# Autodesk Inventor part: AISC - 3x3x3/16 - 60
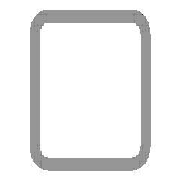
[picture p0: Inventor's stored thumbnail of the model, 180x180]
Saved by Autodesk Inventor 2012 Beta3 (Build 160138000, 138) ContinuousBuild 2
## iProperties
IsCustomPart: 1
Created: 2011-01
Part Number: AISC - 3x3x3/16 - 60
Material: Steel, Mild
Description: Tube
Document SubType Name: Modeling
Standard: ANSI
Designer: Beta-8540w
Standards Organization: ANSI
Language: en-US
Size Designation: 3x3x3/16
Categories: <MemberInstance><Categories><Category DisplayName="Structural Shapes" InternalName="089c4875-fa83-4c05-b084-43b9cc11f5ed" Mnemonic="GRDR"><CategoryParameter Dis
Stock Number: 3x3x3/16
Density: 7.86 g/cm^3
G_L: 60.000 in
G_W: 3.000 in
G_H: 3.000 in
_CCFamilyMember: 9
_CCFamilyDisplayName: ANSI AISC (Square) - Tube
_FrameMemberDoc: Frame Member File
_Version: 15.0.0
_GetPNFromCC: 1
Author: Beta-8540w
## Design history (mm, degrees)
node "Start plane"
node "End plane"
sketch "Sketch"
  geometry: L1 (-38.1, -28.575)-(-38.1, 28.575); L2 (-28.575, 38.1)-(28.575, 38.1); L3 (38.1, 28.575)-(38.1, -28.575); L4 (28.575, -38.1)-(-28.575, -38.1); L5 (-28.575, 33.337)-(28.575, 33.338); L6 (33.338, 28.575)-(33.338, -28.575); L7 (28.575, -33.337)-(-28.575, -33.338); L8 (-33.338, -28.575)-(-33.338, 28.575); L9 (0, 56.102)-(0, -56.102) reference; L10 (-56.102, 0)-(56.102, 0) reference; A1 r 9.525 centre (-28.575, -28.575) between (-38.1, -28.575) and (-28.575, -38.1); A2 r 9.525 centre (-28.575, 28.575) between (-28.575, 38.1) and (-38.1, 28.575); A3 r 9.525 centre (28.575, 28.575) between (38.1, 28.575) and (28.575, 38.1); A4 r 9.525 centre (28.575, -28.575) between (28.575, -38.1) and (38.1, -28.575); A5 r 4.763 centre (-28.575, 28.575) between (-28.575, 33.337) and (-33.338, 28.575); A6 r 4.763 centre (28.575, 28.575) between (33.338, 28.575) and (28.575, 33.338); A7 r 4.763 centre (28.575, -28.575) between (28.575, -33.337) and (33.338, -28.575); A8 r 4.763 centre (-28.575, -28.575) between (-33.338, -28.575) and (-28.575, -33.338)
  constraints: 16 end point, 16 point on circle, 8 centre point, 8 tangent, 4 parallel, 3 equal radius, 2 perpendicular, 7 other
  dimensions: "d10" = 76.2 distance between parallel lines of L2 L4 (= G_H); "d11" = 76.2 distance between parallel lines of L1 L3 (= G_W); "d12" = 4.7625 distance between parallel lines of L3 L6 (= G_T); "d15" = 38.1 distance between parallel lines of L2 L10 (= 0.5 x d10); "d16" = 38.1 distance between parallel lines of L9 L3 (= 0.5 x d11); "d17" = 9.525 radius of A1 (= G_IR)
extrude "Body" new body sketch "Sketch" stored distance "d3" = 1524 (= G_L); taper "d4" = 0 deg
node "Driven Length"
  sketch "Sketch3"
    geometry: L1 (0, 0)-(10, 0) reference
    constraints: 2 end point, 1 horizontal
  workplane "Work Plane3"
  sketch "Sketch4"
    geometry: L1 (-2, 0)-(12, 0) reference; L2 (-2, 1524)-(12, 1524) reference
    dimensions: "d19" = 1524 distance between parallel lines of L1 L2 (derived)
body "Solid1"
other parameters: "G_W" = 76.2 [user parameter; used in 1 equation term], "G_H" = 76.2 [user parameter; used in 1 equation term], "G_T" = 4.7625 [user parameter; used in 1 equation term], "G_IR" = 9.525 [user parameter; used in 1 equation term], "G_L" = 1524 (= d19) [user parameter; used in 1 equation term], "G_OFFSET_START" = 0 [user parameter; used in 1 equation term], "G_OFFSET_END" = 0 [user parameter; used in 1 equation term], "d13" = 0 (computed from G_OFFSET_START), "d14" = 1524 (= G_OFFSET_END + B_L), "B_L" = 1524 [user parameter; used in 1 equation term], "d18" = 90 deg
